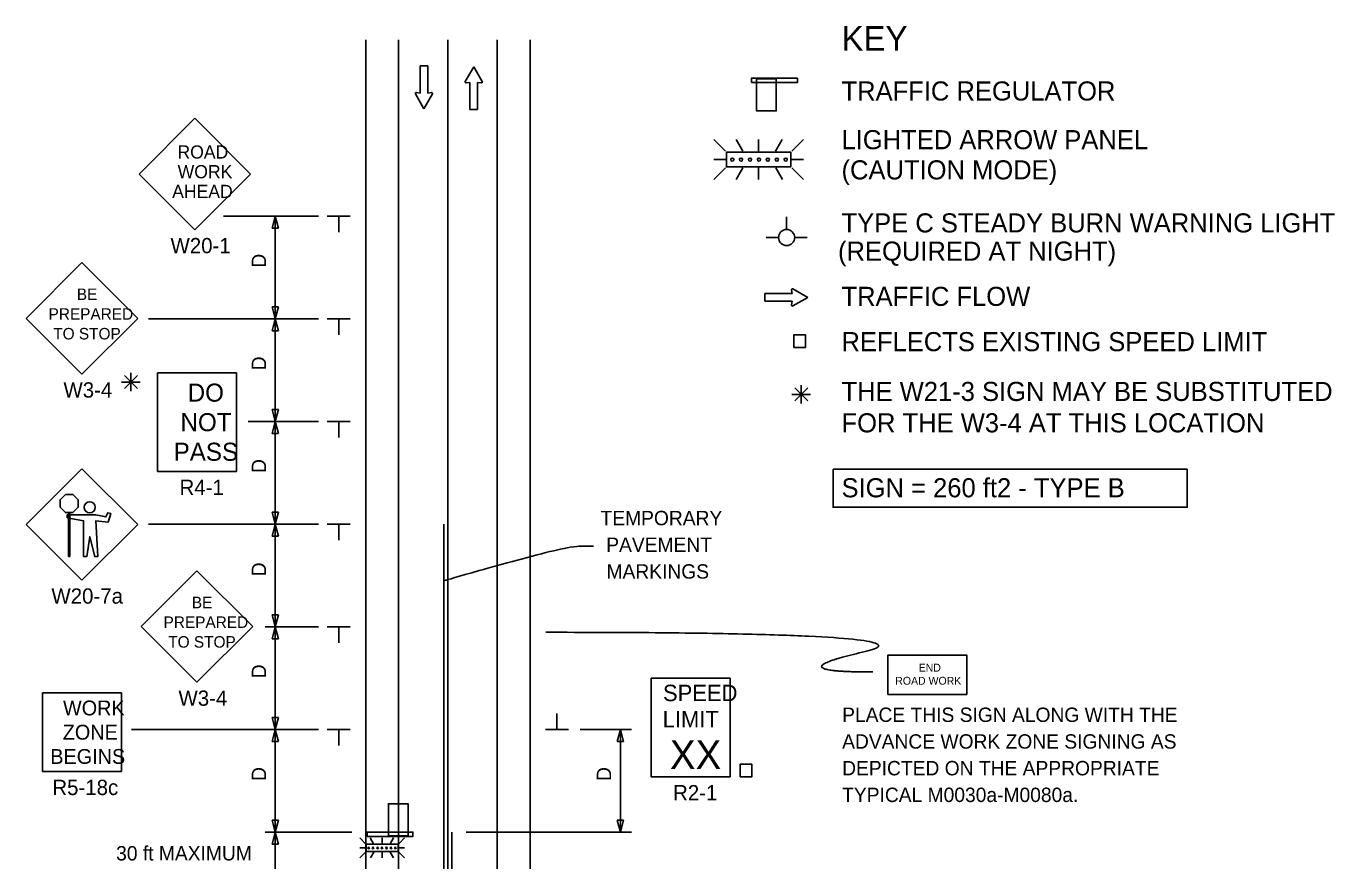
# Model space of a CAD drawing. Extents: x 16735 to 18477, y 4638 to 5631.
# Drawn here: x 16770 to 17407, y 5224 to 5631 of the extents above; entities that cross this region are included whole.
import ezdxf

# ---------------------------------------------------------------- set-up
doc = ezdxf.new("R2010")
doc.units = 0
for name, color, linetype in [('ALI_LEGAL_EX', 7, 'Continuous'), ('MT_SCRATCH_LEVEL_E', 7, 'Continuous'), ('PAVT_EDGE_EX', 7, 'Continuous'), ('TRAFFIC_SIGNS_PR', 7, 'Continuous'), ('TYPICAL_TEXT_DIMEN_EX', 7, 'Continuous'), ('TYPICAL_TEXT_DIMEN_PR', 7, 'Continuous')]:
    doc.layers.add(name, color=color, linetype=linetype)

msp = doc.modelspace()

# ---------------------------------------------------------------- linework, layer by layer
at = {"layer": 'ALI_LEGAL_EX'}
for p, q in [((16973.59, 5387.98), (16973.59, 5163)), ((16977.59, 5237.98), (16977.59, 5013))]:
    msp.add_line(p, q, dxfattribs=at)
at = {"layer": 'MT_SCRATCH_LEVEL_E'}
for p, q in [((16965.79, 5611.17), (16962.05, 5611.17)), ((16962.05, 5611.17), (16962.05, 5597.91)), ((16965.79, 5611.17), (16962.05, 5611.17)), ((16962.05, 5611.17), (16962.05, 5597.91)), ((16965.79, 5597.91), (16965.79, 5611.17)), ((16965.79, 5597.91), (16965.79, 5611.17)), ((16988.18, 5610.81), (16984.07, 5603.57)), ((16988.18, 5610.81), (16984.07, 5603.57)), ((16992.33, 5603.57), (16988.18, 5610.81)), ((16992.33, 5603.57), (16988.18, 5610.81)), ((16984.55, 5602.88), (16986.33, 5603.2)), ((16984.55, 5602.88), (16986.33, 5603.2)), ((16986.33, 5603.2), (16986.33, 5589.94)), ((16986.33, 5603.2), (16986.33, 5589.94)), ((16990.07, 5589.94), (16990.07, 5603.2)), ((16990.07, 5603.2), (16991.85, 5602.88)), ((16990.07, 5589.94), (16990.07, 5603.2)), ((16990.07, 5603.2), (16991.85, 5602.88)), ((16959.79, 5597.55), (16963.94, 5590.31)), ((16959.79, 5597.55), (16963.94, 5590.31)), ((16962.05, 5597.91), (16960.27, 5598.23)), ((16962.05, 5597.91), (16960.27, 5598.23)), ((16963.94, 5590.31), (16968.05, 5597.55)), ((16963.94, 5590.31), (16968.05, 5597.55)), ((16967.57, 5598.23), (16965.79, 5597.91)), ((16967.57, 5598.23), (16965.79, 5597.91)), ((16986.33, 5589.94), (16990.07, 5589.94)), ((16986.33, 5589.94), (16990.07, 5589.94)), ((17143.25, 5500.31), (17129.99, 5500.31)), ((17129.99, 5500.31), (17129.99, 5496.57)), ((17143.25, 5500.31), (17129.99, 5500.31)), ((17129.99, 5500.31), (17129.99, 5496.57)), ((17142.93, 5502.09), (17143.25, 5500.31)), ((17142.93, 5502.09), (17143.25, 5500.31)), ((17150.86, 5498.46), (17143.62, 5502.57)), ((17150.86, 5498.46), (17143.62, 5502.57)), ((17129.99, 5496.57), (17143.25, 5496.57)), ((17129.99, 5496.57), (17143.25, 5496.57)), ((17143.25, 5496.57), (17142.93, 5494.79)), ((17143.25, 5496.57), (17142.93, 5494.79)), ((17143.62, 5494.31), (17150.86, 5498.46)), ((17143.62, 5494.31), (17150.86, 5498.46))]:
    msp.add_line(p, q, dxfattribs=at)
for centre, start, end in [((16984.48, 5603.34), 150.42484, 279.96381), ((16984.48, 5603.34), 150.42484, 279.96381), ((16991.92, 5603.34), 260.03619, 29.77312), ((16991.92, 5603.34), 260.03619, 29.77312), ((16960.2, 5597.77), 80.03619, 209.77312), ((16960.2, 5597.77), 80.03619, 209.77312), ((16967.64, 5597.77), 330.42484, 99.96381), ((16967.64, 5597.77), 330.42484, 99.96381), ((17143.39, 5502.16), 60.42484, 189.96381), ((17143.39, 5502.16), 60.42484, 189.96381), ((17143.4, 5494.72), 170.03619, 299.77312), ((17143.4, 5494.72), 170.03619, 299.77312)]:
    msp.add_arc(centre, 0.463, start, end, dxfattribs=at)
at = {"layer": 'PAVT_EDGE_EX'}
for p, q in [((16935.59, 5623.96), (16935.59, 4802.04)), ((16951.59, 5623.96), (16951.59, 4802.04)), ((16975.59, 5623.96), (16975.59, 4802.04)), ((16999.59, 5623.96), (16999.59, 4802.04)), ((17015.59, 5623.96), (17015.59, 4802.04))]:
    msp.add_line(p, q, dxfattribs=at)
for points in [[(16975.59, 5623.96), (16975.59, 5598.96)], [(16975.59, 5523.96), (16975.59, 5498.96)], [(16975.59, 5423.96), (16975.59, 5398.96)], [(16975.59, 5323.96), (16975.59, 5298.96)]]:
    msp.add_lwpolyline(points, dxfattribs=at)
at = {"layer": 'TRAFFIC_SIGNS_PR'}
for p, q in [((17125.87, 5604.92), (17125.87, 5589.31)), ((17135.46, 5604.92), (17135.46, 5589.31)), ((17125.87, 5589.31), (17135.46, 5589.31)), ((16852.4, 5585.7), (16825.25, 5558.55)), ((16879.56, 5558.55), (16852.4, 5585.7)), ((17105.1, 5575.28), (17110.74, 5569.64)), ((17119.28, 5569.64), (17116.02, 5575.28)), ((17126.91, 5569.64), (17126.91, 5575.28)), ((17135.18, 5569.64), (17138.43, 5575.28)), ((17143.08, 5569.64), (17148.72, 5575.28)), ((17110.74, 5565.58), (17105.1, 5565.58)), ((17114.01, 5565.58), (17114.01, 5565.58)), ((17118.36, 5565.58), (17118.36, 5565.58)), ((17122.71, 5565.58), (17122.71, 5565.58)), ((17127.06, 5565.58), (17127.06, 5565.58)), ((17131.4, 5565.58), (17131.4, 5565.58)), ((17135.75, 5565.58), (17135.75, 5565.58)), ((17140.1, 5565.58), (17140.1, 5565.58)), ((17143.08, 5565.58), (17148.72, 5565.58)), ((16825.25, 5558.55), (16852.4, 5531.4)), ((16852.4, 5531.4), (16879.56, 5558.55)), ((17105.1, 5555.88), (17110.74, 5561.51)), ((17115.97, 5555.87), (17119.22, 5561.51)), ((17126.91, 5561.51), (17126.91, 5555.87)), ((17138.48, 5555.87), (17135.23, 5561.51)), ((17143.08, 5561.51), (17148.72, 5555.87)), ((17140.54, 5532.06), (17140.54, 5537.68)), ((17136.1, 5527.62), (17130.56, 5527.62)), ((17144.98, 5527.62), (17150.57, 5527.62)), ((16797.44, 5515.4), (16770.28, 5488.25)), ((16824.59, 5488.25), (16797.44, 5515.4)), ((16770.28, 5488.25), (16797.44, 5461.1)), ((16797.44, 5461.1), (16824.59, 5488.25)), ((16834.28, 5413.68), (16834.28, 5461.68)), ((16834.28, 5461.68), (16872.68, 5461.68)), ((16872.68, 5413.68), (16872.68, 5461.68)), ((16797.44, 5415.04), (16770.28, 5387.88)), ((16824.59, 5387.88), (16797.44, 5415.04)), ((16834.28, 5413.68), (16872.68, 5413.68)), ((16770.28, 5387.88), (16797.44, 5360.73)), ((16797.44, 5360.73), (16824.59, 5387.88)), ((16853.44, 5365.3), (16826.28, 5338.14)), ((16880.59, 5338.14), (16853.44, 5365.3)), ((16826.28, 5338.14), (16853.44, 5310.99)), ((16853.44, 5310.99), (16880.59, 5338.14)), ((17074.57, 5312.95), (17112.97, 5312.95)), ((17074.57, 5264.95), (17074.57, 5312.95)), ((17112.97, 5264.95), (17112.97, 5312.95)), ((16778.22, 5267.52), (16778.22, 5305.92)), ((16778.22, 5305.92), (16816.62, 5305.92)), ((16816.62, 5267.52), (16816.62, 5305.92)), ((16778.22, 5267.52), (16816.62, 5267.52)), ((17074.57, 5264.95), (17112.97, 5264.95)), ((16946.65, 5236.26), (16946.65, 5251.87)), ((16956.24, 5251.87), (16946.65, 5251.87)), ((16956.24, 5236.26), (16956.24, 5251.87)), ((16935.53, 5232.35), (16932.71, 5235.17)), ((16937.83, 5235.17), (16939.46, 5232.35)), ((16943.62, 5232.35), (16943.62, 5235.17)), ((16949.09, 5235.17), (16947.46, 5232.35)), ((16954.52, 5235.17), (16951.7, 5232.35)), ((16935.53, 5230.32), (16932.71, 5230.32)), ((16935.53, 5228.29), (16932.71, 5225.47)), ((16937.02, 5230.32), (16937.02, 5230.32)), ((16939.48, 5228.29), (16937.85, 5225.47)), ((16939.2, 5230.32), (16939.2, 5230.32)), ((16941.37, 5230.32), (16941.37, 5230.32)), ((16943.54, 5230.32), (16943.54, 5230.32)), ((16943.62, 5228.29), (16943.62, 5225.47)), ((16945.72, 5230.32), (16945.72, 5230.32)), ((16947.43, 5228.29), (16949.06, 5225.47)), ((16947.89, 5230.32), (16947.89, 5230.32)), ((16950.07, 5230.32), (16950.07, 5230.32)), ((16951.7, 5230.32), (16954.52, 5230.32)), ((16954.52, 5225.47), (16951.7, 5228.29))]:
    msp.add_line(p, q, dxfattribs=at)
for points in [[(17145.87, 5605.25), (17123.48, 5605.25), (17123.48, 5603.14), (17145.87, 5603.14)], [(17125.87, 5604.92), (17135.46, 5604.92), (17135.46, 5589.31), (17125.87, 5589.31)], [(17142.62, 5561.98), (17111.2, 5561.98), (17111.2, 5569.18), (17142.62, 5569.18)], [(17144.07, 5474.1), (17149.66, 5474.1), (17149.66, 5480.27), (17144.07, 5480.27)], [(16789.4, 5402.52), (16793.07, 5402.52), (16795.67, 5399.92), (16795.67, 5396.24), (16793.07, 5393.65), (16789.4, 5393.65), (16786.8, 5396.24), (16786.8, 5399.92)], [(16804.12, 5392.6), (16790.3, 5392.6), (16790.3, 5391.1), (16798.26, 5389.65), (16798.26, 5372.25), (16799.76, 5372.25), (16801.26, 5381.85), (16803.66, 5372.25), (16805.16, 5372.25), (16804.26, 5389.65), (16810.26, 5389.05), (16811.46, 5393.25), (16810.01, 5393.61), (16809.11, 5391.51)], [(16790.94, 5393.65), (16790.94, 5372.27), (16791.53, 5372.27), (16791.53, 5393.65)], [(17189.81, 5305.07), (17228.21, 5305.07), (17228.21, 5324.27), (17189.81, 5324.27)], [(17117.99, 5264.95), (17123.58, 5264.95), (17123.58, 5271.12), (17117.99, 5271.12)], [(16956.24, 5236.26), (16946.65, 5236.26), (16946.65, 5251.87), (16956.24, 5251.87)], [(16936.24, 5235.93), (16958.62, 5235.93), (16958.62, 5238.03), (16936.24, 5238.03)], [(16935.76, 5232.12), (16951.47, 5232.12), (16951.47, 5228.52), (16935.76, 5228.52)]]:
    msp.add_lwpolyline(points, close=True, dxfattribs=at)
for centre, radius in [((17114.05, 5565.58), 0.758), ((17118.36, 5565.58), 0.758), ((17122.71, 5565.58), 0.758), ((17127.06, 5565.58), 0.758), ((17131.4, 5565.58), 0.758), ((17135.75, 5565.58), 0.758), ((17140.1, 5565.58), 0.758), ((17140.54, 5527.62), 3.91), ((16801.24, 5396.22), 2.7), ((16937.02, 5230.32), 0.379), ((16939.2, 5230.32), 0.379), ((16941.37, 5230.32), 0.379), ((16943.54, 5230.32), 0.379), ((16945.72, 5230.32), 0.379), ((16947.89, 5230.32), 0.379), ((16950.05, 5230.32), 0.379)]:
    msp.add_circle(centre, radius, dxfattribs=at)
msp.add_open_spline([(17182.44, 5316.01), (17135.2, 5316.01), (17220.22, 5335.36), (17023.25, 5335.36)], degree=2, dxfattribs=at)
at = {"layer": 'TYPICAL_TEXT_DIMEN_EX'}
msp.add_lwpolyline([(17163.19, 5414.78), (17335.58, 5414.78), (17335.58, 5396.22), (17163.19, 5396.22)], close=True, dxfattribs=at)
at = {"layer": 'TYPICAL_TEXT_DIMEN_PR'}
for p, q in [((16866.43, 5537.98), (16912.59, 5537.98)), ((16890.02, 5532.12), (16891.59, 5537.98)), ((16891.59, 5537.98), (16891.59, 5487.98)), ((16891.59, 5537.98), (16893.16, 5532.12)), ((16916.84, 5537.98), (16928.09, 5537.98)), ((16922.47, 5537.98), (16922.47, 5530.19)), ((16891.59, 5532.12), (16890.02, 5532.12)), ((16893.16, 5532.12), (16891.59, 5532.12)), ((16891.59, 5487.98), (16890.02, 5493.84)), ((16890.02, 5493.84), (16891.59, 5493.84)), ((16891.59, 5493.84), (16893.16, 5493.84)), ((16893.16, 5493.84), (16891.59, 5487.98)), ((16829.89, 5487.98), (16912.59, 5487.98)), ((16890.02, 5482.12), (16891.59, 5487.98)), ((16891.59, 5487.98), (16891.59, 5437.98)), ((16891.59, 5487.98), (16893.16, 5482.12)), ((16916.84, 5487.98), (16928.09, 5487.98)), ((16922.47, 5487.98), (16922.47, 5480.19)), ((16891.59, 5482.12), (16890.02, 5482.12)), ((16893.16, 5482.12), (16891.59, 5482.12)), ((16818.08, 5460.41), (16824.45, 5454.04)), ((16824.45, 5460.41), (16818.08, 5454.04)), ((16821.26, 5457.22), (16821.26, 5461.68)), ((16821.26, 5457.22), (16816.73, 5457.22)), ((16821.26, 5457.22), (16824.45, 5457.22)), ((16821.26, 5457.22), (16825.74, 5457.22)), ((16821.26, 5457.22), (16821.26, 5452.72)), ((17150.86, 5454.4), (17144.48, 5448.02)), ((17144.49, 5454.4), (17150.86, 5448.02)), ((17147.67, 5451.21), (17147.67, 5455.67)), ((17147.67, 5451.21), (17143.14, 5451.21)), ((17147.67, 5451.21), (17150.86, 5451.21)), ((17147.67, 5451.21), (17152.15, 5451.21)), ((17147.67, 5451.21), (17147.67, 5446.71)), ((16891.59, 5437.98), (16890.02, 5443.84)), ((16890.02, 5443.84), (16891.59, 5443.84)), ((16891.59, 5443.84), (16893.16, 5443.84)), ((16893.16, 5443.84), (16891.59, 5437.98)), ((16878.43, 5437.98), (16912.59, 5437.98)), ((16890.02, 5432.12), (16891.59, 5437.98)), ((16891.59, 5437.98), (16891.59, 5387.98)), ((16891.59, 5437.98), (16893.16, 5432.12)), ((16916.84, 5437.98), (16928.09, 5437.98)), ((16922.47, 5437.98), (16922.47, 5430.19)), ((16891.59, 5432.12), (16890.02, 5432.12)), ((16893.16, 5432.12), (16891.59, 5432.12)), ((16891.59, 5387.98), (16890.02, 5393.84)), ((16890.02, 5393.84), (16891.59, 5393.84)), ((16891.59, 5387.98), (16890.02, 5393.84)), ((16890.02, 5393.84), (16891.59, 5393.84)), ((16891.59, 5393.84), (16893.16, 5393.84)), ((16893.16, 5393.84), (16891.59, 5387.98)), ((16891.59, 5393.84), (16893.16, 5393.84)), ((16893.16, 5393.84), (16891.59, 5387.98)), ((16829.89, 5387.98), (16912.59, 5387.98)), ((16890.02, 5382.12), (16891.59, 5387.98)), ((16891.59, 5387.98), (16891.59, 5337.98)), ((16891.59, 5387.98), (16893.16, 5382.12)), ((16916.84, 5387.98), (16928.09, 5387.98)), ((16922.47, 5387.98), (16922.47, 5380.19)), ((16891.59, 5382.12), (16890.02, 5382.12)), ((16893.16, 5382.12), (16891.59, 5382.12)), ((16891.59, 5337.98), (16890.02, 5343.84)), ((16890.02, 5343.84), (16891.59, 5343.84)), ((16891.59, 5343.84), (16893.16, 5343.84)), ((16893.16, 5343.84), (16891.59, 5337.98)), ((16886.59, 5337.98), (16912.59, 5337.98)), ((16890.02, 5332.12), (16891.59, 5337.98)), ((16891.59, 5337.98), (16893.16, 5332.12)), ((16891.59, 5337.98), (16891.59, 5287.98)), ((16916.84, 5337.98), (16928.09, 5337.98)), ((16922.47, 5337.98), (16922.47, 5330.19)), ((16891.59, 5332.12), (16890.02, 5332.12)), ((16893.16, 5332.12), (16891.59, 5332.12)), ((17028.72, 5287.98), (17028.72, 5295.76)), ((16891.59, 5287.98), (16890.02, 5293.84)), ((16890.02, 5293.84), (16891.59, 5293.84)), ((16891.59, 5293.84), (16893.16, 5293.84)), ((16893.16, 5293.84), (16891.59, 5287.98)), ((16821.64, 5287.98), (16912.59, 5287.98)), ((16890.02, 5282.12), (16891.59, 5287.98)), ((16891.59, 5282.12), (16890.02, 5282.12)), ((16891.59, 5287.98), (16891.59, 5237.98)), ((16891.59, 5287.98), (16893.16, 5282.12)), ((16893.16, 5282.12), (16891.59, 5282.12)), ((16916.84, 5287.98), (16928.09, 5287.98)), ((16922.47, 5287.98), (16922.47, 5280.19)), ((17034.34, 5287.98), (17023.09, 5287.98)), ((17040.05, 5287.98), (17065.03, 5287.98)), ((17058.02, 5282.12), (17059.59, 5287.98)), ((17059.59, 5282.12), (17058.02, 5282.12)), ((17059.59, 5287.98), (17059.59, 5237.98)), ((17059.59, 5287.98), (17061.16, 5282.12)), ((17061.16, 5282.12), (17059.59, 5282.12)), ((16891.59, 5237.98), (16890.02, 5243.84)), ((16890.02, 5243.84), (16891.59, 5243.84)), ((16891.59, 5243.84), (16893.16, 5243.84)), ((16893.16, 5243.84), (16891.59, 5237.98)), ((17059.59, 5237.98), (17058.02, 5243.84)), ((17058.02, 5243.84), (17059.59, 5243.84)), ((17059.59, 5243.84), (17061.16, 5243.84)), ((17061.16, 5243.84), (17059.59, 5237.98)), ((16886.59, 5237.98), (16928.82, 5237.98)), ((16890.02, 5232.12), (16891.59, 5237.98)), ((16891.59, 5237.98), (16891.59, 5217.98)), ((16891.59, 5237.98), (16893.16, 5232.12)), ((16984.48, 5237.98), (17065.03, 5237.98)), ((16891.59, 5232.12), (16890.02, 5232.12)), ((16893.16, 5232.12), (16891.59, 5232.12))]:
    msp.add_line(p, q, dxfattribs=at)
msp.add_open_spline([(16973.69, 5360.42), (16975.56, 5360.95), (16985.13, 5363.86), (17034.07, 5377.31), (17041.57, 5377.31), (17046.44, 5377.31), (17046.44, 5377.31)], degree=3, dxfattribs=at)

# ---------------------------------------------------------------- texts
at = {"layer": 'TRAFFIC_SIGNS_PR'}
for s, height, p in [('ROAD', 6.4, (16843.95, 5566.09)), ('WORK', 6.4, (16844.05, 5556.49)), ('AHEAD', 6.4, (16841.36, 5546.89)), ('W20-1', 7.44, (16840.57, 5519.96)), ('BE', 5.6, (16794.94, 5497.18)), ('PREPARED', 5.6, (16781.18, 5487.58)), ('TO STOP', 5.6, (16783.46, 5477.98)), ('W3-4', 7.44, (16788.44, 5449.66)), ('DO', 8.8, (16848.91, 5447.68)), ('NOT', 8.8, (16845.43, 5433.28)), ('PASS', 8.8, (16842.08, 5418.88)), ('R4-1', 7.44, (16844.96, 5402.24)), ('W20-7a', 7.44, (16782.58, 5349.29)), ('BE', 5.6, (16850.94, 5347.07)), ('PREPARED', 5.6, (16837.18, 5337.47)), ('TO STOP', 5.6, (16839.46, 5327.87)), ('END', 3.831, (17204.82, 5316.2)), ('SPEED', 8, (17080.34, 5301.81)), ('ROAD WORK', 3.831, (17193.42, 5309.82)), ('WORK', 7.217, (16788.22, 5294.89)), ('W3-4', 7.44, (16844.44, 5299.55)), ('LIMIT', 8, (17080.18, 5289.01)), ('PLACE THIS SIGN ALONG WITH THE', 7, (17167.56, 5291.68)), ('ZONE', 7.217, (16788.1, 5283.07)), ('XX', 14.031, (17083.68, 5268.7)), ('ADVANCE WORK ZONE SIGNING AS', 7, (17167.56, 5278.68)), ('BEGINS', 7.217, (16782.03, 5271.27)), ('DEPICTED ON THE APPROPRIATE', 7, (17167.56, 5265.68)), ('R5-18c', 7.44, (16783.03, 5256.08)), ('R2-1', 7.44, (17085.25, 5253.51)), ('TYPICAL M0030a-M0080a.', 7, (17167.56, 5252.68))]:
    msp.add_text(s, height=height, dxfattribs=at).set_placement(p)
at = {"layer": 'TYPICAL_TEXT_DIMEN_EX'}
for s, height, p in [('KEY', 12, (17167.26, 5618.56)), ('TRAFFIC REGULATOR', 9.3, (17167.26, 5594.35)), ('LIGHTED ARROW PANEL', 9.3, (17167.26, 5570.62)), ('(CAUTION MODE)', 9.3, (17167.26, 5555.92)), ('TYPE C STEADY BURN WARNING LIGHT', 9.3, (17167.26, 5530.09)), ('(REQUIRED AT NIGHT)', 9.3, (17165.56, 5516.36)), ('TRAFFIC FLOW', 9.3, (17167.26, 5494.31)), ('REFLECTS EXISTING SPEED LIMIT', 9.3, (17167.23, 5472.26)), ('THE W21-3 SIGN MAY BE SUBSTITUTED', 9.3, (17167.26, 5448.02)), ('FOR THE W3-4 AT THIS LOCATION', 9.3, (17167.26, 5432.72)), ('SIGN = 260 ft2 - TYPE B', 9.3, (17167.26, 5401.09))]:
    msp.add_text(s, height=height, dxfattribs=at).set_placement(p)
at = {"layer": 'TYPICAL_TEXT_DIMEN_PR'}
for p in [(16887.07, 5512.95), (16887.07, 5462.95), (16887.07, 5412.95), (16887.07, 5362.62), (16887.07, 5312.95), (16887.07, 5262.95), (17055.07, 5262.95)]:
    msp.add_text('D', height=7, rotation=90, dxfattribs=at).set_placement(p)
for s, p in [('TEMPORARY', (17049.92, 5387.49)), ('PAVEMENT', (17052.7, 5374.49)), ('MARKINGS', (17052.84, 5361.49)), ('30 ft MAXIMUM', (16814.08, 5224.21))]:
    msp.add_text(s, height=7, dxfattribs=at).set_placement(p)

doc.saveas('drawing.dxf')
